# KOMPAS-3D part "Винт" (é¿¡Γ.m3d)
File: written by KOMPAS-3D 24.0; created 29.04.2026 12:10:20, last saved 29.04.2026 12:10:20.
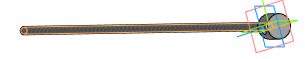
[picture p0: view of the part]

Document properties: Автор: USG_411; Полное имя файла: C:\Users\USG_411\Desktop\ИА-2904_411-12\Винт.m3d

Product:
- Part/product: Винт
    Масса: 0.510687

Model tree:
1. Эскиз:1
2. Элемент выдавливания:1
     Расстояние 2 = 645
3. Условное изображение резьбы:1  (with: Грань.Элемент выдавливания:1, Ребро.Элемент выдавливания:1)  (labels: M10; cil0_24705-2004 coarse)
     Длина резьбы = 645; Шаг резьбы = 1.5; Номинальный диаметр резьбы = 10
4. Подгонка:1  (with: Грань.Элемент выдавливания:1)
5. Эскиз:2  (with: Грань.Элемент выдавливания:1)
6. Элемент выдавливания:2
     Расстояние 1 = 25
7. Эскиз:3
8. Элемент выдавливания:4
     Расстояние 1 = 15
